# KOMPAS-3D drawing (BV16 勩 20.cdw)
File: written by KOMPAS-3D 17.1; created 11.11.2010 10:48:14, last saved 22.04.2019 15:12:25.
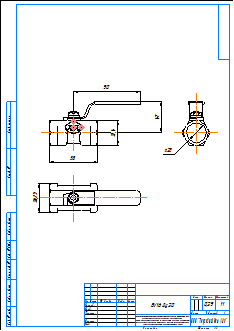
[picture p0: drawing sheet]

Sheet 1: A3, portrait

Title block, sheet 1: name: BV16 Ду 20; material: Внимание! Данный продукт является объектом авторского права ООО «Торговый Дом АДЛ». / Запрещается изменение, копирование, распространение / (в том числе путем копирования на другие сайты и ресурсы в Интернете) / или любое иное использование информации и объектов без предварительного / согласия правообладателя (ООО «Торговый Дом АДЛ»).; mass: 0,29; scale: 1:1; sheets: 1; organisation: ООО "Торговый дом АДЛ"; sheet format: A3; stored path: \\adlc.lan\data\АДЛ_ПКД\3D-модели\ADL production\Краны шаровые серии BV\BV16\KOMPAS 2D\BV16 Ду 20.cdw

Views: Спереди 1, Проекционный вид 2, Проекционный вид 3
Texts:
  user
  adl
Dimensions and other numbers on the sheet: 58; 31,4; 90; 47; 25; 36,25; 1:1; 1; 0,29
